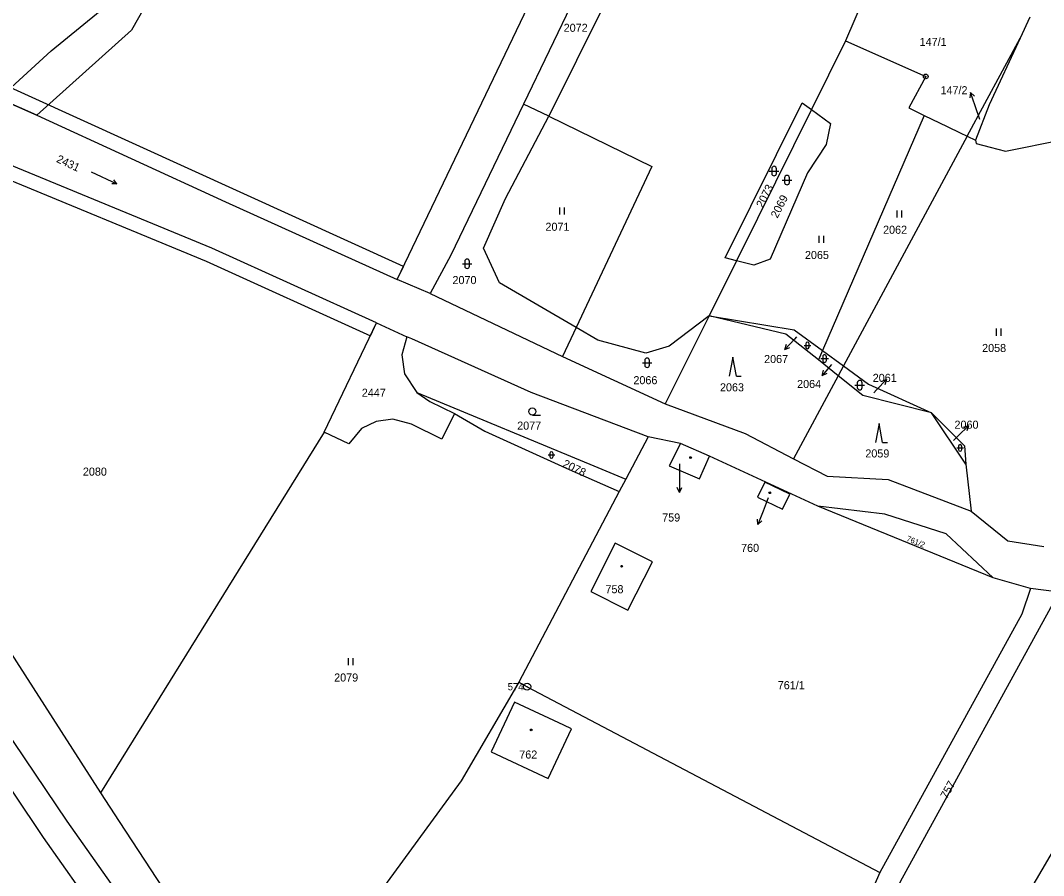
# Model space of a CAD drawing. Extents: x -504988 to -494607, y -1123820 to -1114018.
# Drawn here: x -502079.2 to -501863.6, y -1120941.2 to -1120761 of the extents above; entities that cross this region are included whole.
import ezdxf

# ---------------------------------------------------------------- set-up
doc = ezdxf.new("R2010")
doc.units = 0
for name, color, linetype in [('Hranice parcel', 7, 'Continuous'), ('Parcelní čísla', 7, 'Continuous'), ('Pop  PČ popisy', 7, 'Continuous'), ('Věcná břemena k části', 7, 'Continuous'), ('Značky bodu BP', 7, 'Continuous'), ('Značky budov', 7, 'Continuous'), ('Značky kultur', 7, 'Continuous')]:
    doc.layers.add(name, color=color, linetype=linetype)

msp = doc.modelspace()

# ---------------------------------------------------------------- linework, layer by layer
at = {"layer": 'Hranice parcel'}
for p, q in [((-501950.46, -1120731.33), (-501973.19, -1120778.6)), ((-501894.68, -1120740.44), (-501905.31, -1120765.23)), ((-501866.48, -1120760.29), (-501868.51, -1120764.69)), ((-501905.31, -1120765.23), (-501912.49, -1120779.73)), ((-501879.66, -1120785.38), (-501868.51, -1120764.69)), ((-502075.76, -1120780.96), (-502083.81, -1120777.38)), ((-501967.89, -1120781.15), (-501973.19, -1120778.6)), ((-501888.71, -1120780.98), (-501910.17, -1120830.55)), ((-501879.66, -1120785.38), (-501905.75, -1120833.78)), ((-501879.66, -1120785.38), (-501877.92, -1120786.23)), ((-501928.3, -1120811.62), (-501934.05, -1120823.23)), ((-501992.88, -1120818.54), (-501999.8, -1120815.57)), ((-501992.88, -1120818.54), (-501964.97, -1120831.78)), ((-502015.21, -1120847.77), (-502004.18, -1120824.73)), ((-502004.18, -1120824.73), (-501997.8, -1120827.63)), ((-501934.05, -1120823.23), (-501943.35, -1120841.74)), ((-501962.1, -1120825.68), (-501964.97, -1120831.78)), ((-501910.17, -1120830.55), (-501911.03, -1120832.53)), ((-501910.17, -1120830.55), (-501905.75, -1120833.78)), ((-501964.97, -1120831.78), (-501943.35, -1120841.74)), ((-501906.86, -1120835.84), (-501911.03, -1120832.53)), ((-501905.75, -1120833.78), (-501906.86, -1120835.84)), ((-501906.86, -1120835.84), (-501916.29, -1120853.34)), ((-501879.96, -1120854.51), (-501887.17, -1120843.64)), ((-502015.21, -1120847.77), (-502062.34, -1120923.76)), ((-501946.93, -1120848.74), (-501951.63, -1120857.66)), ((-501940.07, -1120850.16), (-501946.93, -1120848.74)), ((-501934.01, -1120852.79), (-501940.07, -1120850.16)), ((-501911.16, -1120863.36), (-501934.01, -1120852.79)), ((-501879.96, -1120854.51), (-501878.85, -1120864.39)), ((-501951.63, -1120857.66), (-501953, -1120860.25)), ((-501953, -1120860.25), (-501974.18, -1120900.43)), ((-501874.18, -1120878.48), (-501911.16, -1120863.36)), ((-501866.29, -1120880.69), (-501874.18, -1120878.48)), ((-501860.27, -1120881.48), (-501866.29, -1120880.69)), ((-501834.14, -1120889.09), (-501926.63, -1121046.93))]:
    msp.add_line(p, q, dxfattribs=at)
for points in [[(-501999.8, -1120815.57), (-501942.96, -1120696.87), (-501939.46, -1120690.2), (-501936.45, -1120685.28), (-501916.12, -1120653.96), (-501915.3, -1120651.99), (-501915.16, -1120650.68), (-501915.2, -1120650.28)], [(-502083.81, -1120777.38), (-502072.75, -1120767.36), (-502059.77, -1120756.76), (-502044.7, -1120730.83), (-502042.28, -1120726.74)], [(-502036.76, -1120729.34), (-502055.8, -1120763.01), (-502075.76, -1120780.96)], [(-501950.46, -1120731.33), (-501950.45, -1120746.03), (-501967.89, -1120781.15)], [(-501905.31, -1120765.23), (-501888.41, -1120772.77), (-501891.97, -1120779.39), (-501888.71, -1120780.98)], [(-501868.51, -1120764.69), (-501875.02, -1120778.75), (-501877.92, -1120786.23)], [(-502004.18, -1120824.73), (-502038.87, -1120808.96), (-502083.06, -1120790.73), (-502128.43, -1120766.97)], [(-501973.19, -1120778.6), (-501988.51, -1120810.47), (-501992.88, -1120818.54)], [(-501928.3, -1120811.62), (-501930.66, -1120811), (-501914.44, -1120778.3), (-501912.49, -1120779.73)], [(-502075.76, -1120780.96), (-502036, -1120799.21), (-501999.8, -1120815.57)], [(-501962.1, -1120825.68), (-501978.23, -1120816.29), (-501981.62, -1120808.96), (-501976.97, -1120798.52), (-501967.89, -1120781.15)], [(-501967.89, -1120781.15), (-501946.11, -1120791.72), (-501962.1, -1120825.68)], [(-501912.49, -1120779.73), (-501908.5, -1120782.66), (-501909.36, -1120787.1), (-501913.35, -1120793.06), (-501921.21, -1120811.25), (-501924.64, -1120812.58), (-501928.3, -1120811.62)], [(-501912.49, -1120779.73), (-501923.89, -1120802.73), (-501928.3, -1120811.62)], [(-501888.71, -1120780.98), (-501883.86, -1120783.34), (-501881.13, -1120784.67), (-501879.66, -1120785.38)], [(-501877.92, -1120786.23), (-501877.8, -1120786.9), (-501874.79, -1120787.7), (-501871.6, -1120788.54), (-501847.83, -1120783.72)], [(-502154.7, -1120795.46), (-502132.76, -1120819.41), (-502131.82, -1120820.44), (-502114.44, -1120842.7), (-502062.34, -1120923.76)], [(-501934.05, -1120823.23), (-501942.48, -1120829.62), (-501947.39, -1120831.07), (-501957.53, -1120828.35), (-501962.1, -1120825.68)], [(-501911.03, -1120832.53), (-501917.93, -1120827.07), (-501934.05, -1120823.23)], [(-501934.05, -1120823.23), (-501916.14, -1120826.19), (-501910.17, -1120830.55)], [(-502139, -1120826.63), (-502069.47, -1120929.75), (-502031.69, -1120983.29), (-502011.4, -1121005.07), (-501991.14, -1121023.41), (-501970.68, -1121040), (-501964.47, -1121048.83), (-501953.99, -1121053.79), (-501939.86, -1121062.09), (-501910.52, -1121073.17), (-501876.41, -1121086.03), (-501841.36, -1121095.16)], [(-501997.8, -1120827.63), (-501998.84, -1120831.46), (-501998.29, -1120835.47), (-501995.7, -1120839.42)], [(-501946.93, -1120848.74), (-501971.56, -1120839.41), (-501996.76, -1120828.1), (-501997.8, -1120827.63)], [(-501905.75, -1120833.78), (-501900.49, -1120837.62), (-501887.17, -1120843.64)], [(-501887.17, -1120843.64), (-501901.63, -1120839.99), (-501906.86, -1120835.84)], [(-501995.7, -1120839.42), (-501958.35, -1120854.82), (-501951.63, -1120857.66)], [(-501995.7, -1120839.42), (-501992.96, -1120841.25), (-501987.75, -1120843.82)], [(-501943.35, -1120841.74), (-501926.49, -1120848.05), (-501916.29, -1120853.34)], [(-501987.75, -1120843.82), (-501990.4, -1120849.2), (-501996.84, -1120846.03), (-502000.74, -1120845.01), (-502004.29, -1120845.47), (-502007.38, -1120846.99), (-502010.05, -1120850.24), (-502015.21, -1120847.77)], [(-501987.75, -1120843.82), (-501981.32, -1120847.51), (-501963.56, -1120855.62), (-501953, -1120860.25)], [(-501887.17, -1120843.64), (-501880.25, -1120850.6), (-501879.96, -1120854.51)], [(-501940.07, -1120850.16), (-501942.51, -1120854.81), (-501936.11, -1120857.6), (-501934.01, -1120852.79)], [(-501916.29, -1120853.34), (-501909.17, -1120857.03), (-501896.34, -1120857.73), (-501878.85, -1120864.39)], [(-501918.61, -1120863.98), (-501917.05, -1120860.84), (-501922.3, -1120858.29), (-501923.84, -1120861.43), (-501918.61, -1120863.98)], [(-501874.18, -1120878.48), (-501884.12, -1120869.19), (-501897.01, -1120865.06), (-501911.16, -1120863.36)], [(-501878.85, -1120864.39), (-501871.07, -1120870.62), (-501863.51, -1120871.84)], [(-501959.03, -1120881.33), (-501951.18, -1120885.29), (-501946.01, -1120875.08), (-501953.86, -1120871.11), (-501959.03, -1120881.33)], [(-501866.29, -1120880.69), (-501868.15, -1120886.08), (-501898.07, -1120940.59)], [(-501945.82, -1121026.21), (-501921.73, -1120992.61), (-501906.64, -1120969.19), (-501903.89, -1120964.92), (-501893.74, -1120942.43), (-501861.26, -1120883.28)], [(-501974.18, -1120900.43), (-501986.35, -1120921.25), (-502024.79, -1120973.88)], [(-501974.18, -1120900.43), (-501972.43, -1120901.4), (-501898.07, -1120940.59)], [(-501975.1, -1120904.64), (-501980.03, -1120915.14), (-501968.03, -1120920.78), (-501963.1, -1120910.28), (-501964.7, -1120909.52), (-501975.1, -1120904.64)], [(-501967.19, -1121053.96), (-501969.42, -1121051.94), (-501970.97, -1121050.02), (-501974.27, -1121045.33), (-501975.2, -1121044.16), (-501976.27, -1121043.12), (-502018.66, -1121006.74), (-502025.66, -1121000.14), (-502031, -1120994.17), (-502035.73, -1120987.97), (-502074.39, -1120933.18), (-502086.98, -1120914.51)], [(-502062.34, -1120923.76), (-502058.44, -1120929.83), (-502045.21, -1120949.96), (-502024.79, -1120973.88)], [(-501898.07, -1120940.59), (-501907.94, -1120962.9), (-501926.46, -1120990.33), (-501933.79, -1120997.49), (-501942.83, -1121003.14), (-501948.31, -1121006.26), (-501964.12, -1121030.19)]]:
    msp.add_lwpolyline(points, dxfattribs=at)
at = {"layer": 'Pop  PČ popisy'}
for p, q in [((-501878.96, -1120776.14), (-501879.1, -1120777.25)), ((-501877.98, -1120778.98), (-501878.96, -1120776.14)), ((-501878.96, -1120776.14), (-501878.16, -1120776.93)), ((-501876.99, -1120781.82), (-501877.98, -1120778.98)), ((-501916.06, -1120828.11), (-501918.11, -1120830.3)), ((-501915.63, -1120827.66), (-501916.06, -1120828.11)), ((-501918.11, -1120830.3), (-501917.79, -1120829.23)), ((-501918.11, -1120830.3), (-501917.06, -1120829.91)), ((-501908.26, -1120833.5), (-501910.23, -1120835.77)), ((-501910.23, -1120835.77), (-501909.95, -1120834.68)), ((-501910.23, -1120835.77), (-501909.19, -1120835.34)), ((-501898.77, -1120838.84), (-501896.68, -1120836.68)), ((-501896.68, -1120836.68), (-501897.74, -1120837.05)), ((-501896.68, -1120836.68), (-501897.02, -1120837.75)), ((-501899.35, -1120839.43), (-501898.77, -1120838.84)), ((-501881.54, -1120848.53), (-501879.42, -1120846.41)), ((-501879.42, -1120846.41), (-501880.48, -1120846.76)), ((-501879.42, -1120846.41), (-501879.77, -1120847.47)), ((-501882.52, -1120849.51), (-501881.54, -1120848.53)), ((-501940.33, -1120854.44), (-501940.33, -1120857.44)), ((-501940.33, -1120857.44), (-501940.33, -1120860.44)), ((-501940.33, -1120860.44), (-501940.83, -1120859.44)), ((-501940.33, -1120860.44), (-501939.83, -1120859.44)), ((-501921.63, -1120861.6), (-501922.69, -1120864.4)), ((-501922.69, -1120864.4), (-501923.77, -1120867.2)), ((-501923.77, -1120867.2), (-501923.87, -1120866.09)), ((-501923.77, -1120867.2), (-501922.94, -1120866.45))]:
    msp.add_line(p, q, dxfattribs=at)
at = {"layer": 'Věcná břemena k části'}
for points in [[(-502112.06, -1120761.17), (-502112.9, -1120758.6), (-502115.36, -1120762.97), (-502083.81, -1120777.38), (-502075.76, -1120780.96), (-502036, -1120799.21), (-501999.8, -1120815.57), (-501998.5, -1120812.86)], [(-502130.54, -1120769.26), (-502084.33, -1120793.45), (-502040.06, -1120811.71), (-502005.48, -1120827.44), (-502004.18, -1120824.73), (-502038.87, -1120808.96), (-502083.06, -1120790.73), (-502128.43, -1120766.97)]]:
    msp.add_lwpolyline(points, close=True, dxfattribs=at)
at = {"layer": 'Značky bodu BP'}
for centre, radius in [((-501888.41, -1120772.77), 0.5), ((-501888.41, -1120772.77), 0.0303), ((-501972.43, -1120901.4), 0.75), ((-501972.43, -1120901.4), 0.03)]:
    msp.add_circle(centre, radius, dxfattribs=at)
at = {"layer": 'Značky budov'}
for centre in [(-501937.98, -1120853.09), (-501921.28, -1120860.53), (-501952.52, -1120876), (-501971.57, -1120910.5)]:
    msp.add_circle(centre, 0.175, dxfattribs=at)
at = {"layer": 'Značky kultur'}
for p, q in [((-501920.88, -1120792.21), (-501920.88, -1120793.21)), ((-501919.88, -1120793.21), (-501919.88, -1120792.21)), ((-502064.35, -1120792.86), (-502058.91, -1120795.39)), ((-502058.91, -1120795.39), (-502059.58, -1120794.53)), ((-501921.38, -1120792.71), (-501919.38, -1120792.71)), ((-501918.65, -1120794.61), (-501916.65, -1120794.61)), ((-501918.15, -1120794.11), (-501918.15, -1120795.11)), ((-501917.15, -1120795.11), (-501917.15, -1120794.11)), ((-502058.91, -1120795.39), (-502060.01, -1120795.43)), ((-501965.57, -1120801.88), (-501965.57, -1120800.38)), ((-501964.57, -1120801.88), (-501964.57, -1120800.38)), ((-501894.41, -1120802.51), (-501894.41, -1120801.01)), ((-501893.41, -1120802.51), (-501893.41, -1120801.01)), ((-501910.88, -1120807.83), (-501910.88, -1120806.33)), ((-501909.88, -1120807.83), (-501909.88, -1120806.33)), ((-501985.59, -1120811.75), (-501985.59, -1120812.75)), ((-501984.59, -1120812.75), (-501984.59, -1120811.75)), ((-501986.09, -1120812.25), (-501984.09, -1120812.25)), ((-501873.52, -1120827.43), (-501873.52, -1120825.93)), ((-501872.52, -1120827.43), (-501872.52, -1120825.93)), ((-501913.71, -1120829.1), (-501913.71, -1120829.8)), ((-501913.01, -1120829.8), (-501913.01, -1120829.1)), ((-501914.06, -1120829.45), (-501912.66, -1120829.45)), ((-501948.14, -1120833.12), (-501946.14, -1120833.12)), ((-501947.64, -1120832.62), (-501947.64, -1120833.62)), ((-501946.64, -1120833.62), (-501946.64, -1120832.62)), ((-501929.08, -1120831.94), (-501929.83, -1120835.94)), ((-501928.33, -1120835.94), (-501929.08, -1120831.94)), ((-501910.53, -1120832.24), (-501908.93, -1120832.24)), ((-501910.13, -1120831.84), (-501910.13, -1120832.64)), ((-501909.33, -1120832.64), (-501909.33, -1120831.84)), ((-501928.33, -1120835.94), (-501927.33, -1120835.94)), ((-501902.83, -1120837.33), (-501902.83, -1120838.33)), ((-501901.83, -1120838.33), (-501901.83, -1120837.33)), ((-501903.33, -1120837.83), (-501901.33, -1120837.83)), ((-501971.33, -1120844.15), (-501969.58, -1120844.15)), ((-501898.24, -1120845.91), (-501898.99, -1120849.91)), ((-501897.49, -1120849.91), (-501898.24, -1120845.91)), ((-501897.49, -1120849.91), (-501896.49, -1120849.91)), ((-501881.52, -1120850.71), (-501881.52, -1120851.41)), ((-501880.82, -1120851.41), (-501880.82, -1120850.71)), ((-501968, -1120852.56), (-501966.6, -1120852.56)), ((-501967.65, -1120852.21), (-501967.65, -1120852.91)), ((-501966.95, -1120852.91), (-501966.95, -1120852.21)), ((-501881.87, -1120851.06), (-501880.47, -1120851.06)), ((-502010.12, -1120896.89), (-502010.12, -1120895.39)), ((-502009.12, -1120896.89), (-502009.12, -1120895.39))]:
    msp.add_line(p, q, dxfattribs=at)
msp.add_circle((-501971.33, -1120843.4), 0.75, dxfattribs=at)
for centre, radius, start, end in [((-501920.38, -1120792.21), 0.5, 0, 180), ((-501920.38, -1120793.21), 0.5, 180, 359.9879), ((-501917.65, -1120794.11), 0.5, 0, 180), ((-501917.65, -1120795.11), 0.5, 180, 359.9879), ((-501985.09, -1120811.75), 0.5, 0, 180), ((-501985.09, -1120812.75), 0.5, 180, 359.9879), ((-501913.36, -1120829.1), 0.35, 0, 180), ((-501913.36, -1120829.8), 0.35, 180, 359.9879), ((-501947.14, -1120832.62), 0.5, 0, 180), ((-501909.73, -1120831.84), 0.4, 0, 180), ((-501909.73, -1120832.64), 0.4, 180, 359.9879), ((-501947.14, -1120833.62), 0.5, 180, 359.9879), ((-501902.33, -1120837.33), 0.5, 0, 180), ((-501902.33, -1120838.33), 0.5, 180, 359.9879), ((-501881.17, -1120850.71), 0.35, 0, 180), ((-501967.3, -1120852.21), 0.35, 0, 180), ((-501967.3, -1120852.91), 0.35, 180, 359.9879), ((-501881.17, -1120851.41), 0.35, 180, 359.9879)]:
    msp.add_arc(centre, radius, start, end, dxfattribs=at)

# ---------------------------------------------------------------- texts
at = {"layer": 'Parcelní čísla'}
for s, p in [('2072', (-501964.73, -1120763.36)), ('147/1', (-501889.69, -1120766.33)), ('147/2', (-501885.29, -1120776.52)), ('2071', (-501968.57, -1120805.3)), ('2062', (-501897.4, -1120805.93)), ('2065', (-501913.87, -1120811.25)), ('2070', (-501988.17, -1120816.54)), ('2058', (-501876.52, -1120830.85)), ('2067', (-501922.48, -1120833.18)), ('2061', (-501899.58, -1120837.15)), ('2066', (-501950.03, -1120837.64)), ('2063', (-501931.78, -1120839.14)), ('2064', (-501915.52, -1120838.44)), ('2447', (-502007.28, -1120840.28)), ('2077', (-501974.53, -1120847.22)), ('2060', (-501882.34, -1120847.02)), ('2059', (-501901.14, -1120853.08)), ('2080', (-502066.08, -1120856.91)), ('759', (-501943.96, -1120866.58)), ('760', (-501927.33, -1120872.99)), ('758', (-501955.92, -1120881.7)), ('2079', (-502013.11, -1120900.31)), ('761/1', (-501919.6, -1120901.93)), ('762', (-501974.09, -1120916.55))]:
    msp.add_text(s, height=1.7, dxfattribs=at).set_placement(p)
for s, height, rotation, p in [('2431', 1.7, 335, (-502071.81, -1120790.75)), ('2073', 1.7, 63, (-501922.75, -1120800.6)), ('2069', 1.7, 63, (-501919.67, -1120802.79)), ('2078', 1.7, 334, (-501965.1, -1120854.96)), ('761/2', 1.2, 338, (-501892.59, -1120870.64)), ('757', 1.7, 61, (-501883.94, -1120925.18))]:
    msp.add_text(s, height=height, rotation=rotation, dxfattribs=at).set_placement(p)
at = {"layer": 'Značky bodu BP'}
msp.add_text('574', height=1.5, dxfattribs=at).set_placement((-501976.53, -1120902.15))

doc.saveas('drawing.dxf')
